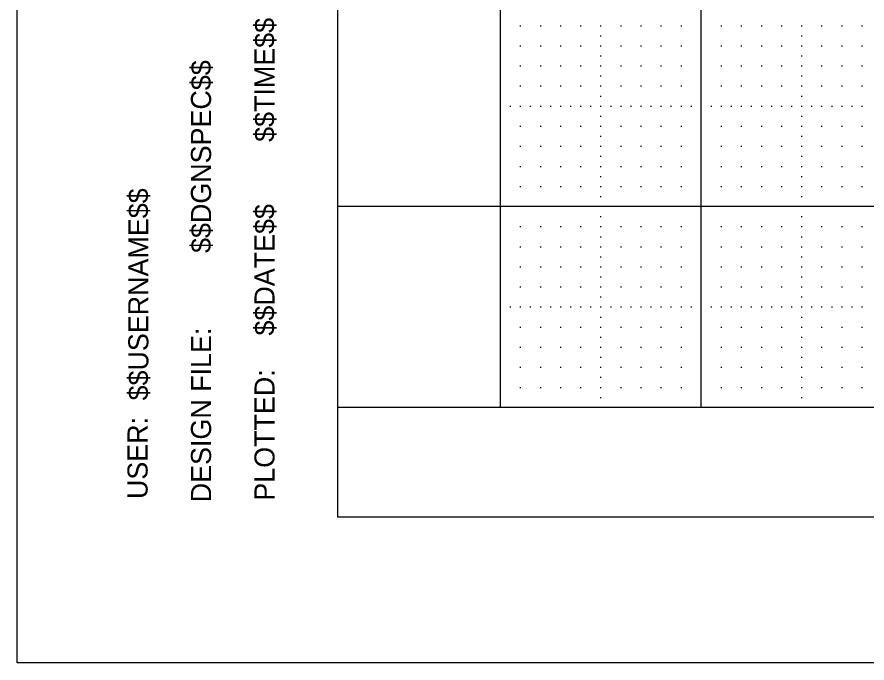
# Model space of a CAD drawing. Extents: x 0 to 34, y 0 to 22.
# Drawn here: x 0 to 4.231, y 0 to 3.215 of the extents above; entities that cross this region are included whole.
import ezdxf

# ---------------------------------------------------------------- set-up
doc = ezdxf.new("R2010")
doc.units = 0
for name, color, linetype in [('Level 1', 7, 'Continuous'), ('Level 4', 7, 'Continuous'), ('Level 5', 7, 'Continuous'), ('Level 63', 7, 'Continuous')]:
    doc.layers.add(name, color=color, linetype=linetype)

msp = doc.modelspace()

# ---------------------------------------------------------------- linework, layer by layer
at = {"layer": 'Level 1'}
for p, q in [((1.597, 0.726), (1.597, 21.272)), ((33.215, 0.726), (1.597, 0.726))]:
    msp.add_line(p, q, dxfattribs=at)
at = {"layer": 'Level 4'}
for p, q in [((2.406, 1.272), (2.406, 21.272)), ((3.406, 1.272), (3.406, 21.272)), ((33.215, 2.272), (1.597, 2.272)), ((33.215, 1.272), (1.597, 1.272))]:
    msp.add_line(p, q, dxfattribs=at)
at = {"layer": 'Level 5'}
for p, q in [((2.5035, 3.172), (2.5085, 3.172)), ((2.6035, 3.172), (2.6085, 3.172)), ((2.7035, 3.172), (2.7085, 3.172)), ((2.8035, 3.172), (2.8085, 3.172)), ((2.9035, 3.172), (2.9085, 3.172)), ((3.0035, 3.172), (3.0085, 3.172)), ((3.1035, 3.172), (3.1085, 3.172)), ((3.2035, 3.172), (3.2085, 3.172)), ((3.3035, 3.172), (3.3085, 3.172)), ((3.5035, 3.172), (3.5085, 3.172)), ((3.6035, 3.172), (3.6085, 3.172)), ((3.7035, 3.172), (3.7085, 3.172)), ((3.8035, 3.172), (3.8085, 3.172)), ((3.9035, 3.172), (3.9085, 3.172)), ((4.0035, 3.172), (4.0085, 3.172)), ((4.1035, 3.172), (4.1085, 3.172)), ((4.2035, 3.172), (4.2085, 3.172)), ((2.9035, 3.122), (2.9085, 3.122)), ((3.9035, 3.122), (3.9085, 3.122)), ((2.5035, 3.072), (2.5085, 3.072)), ((2.6035, 3.072), (2.6085, 3.072)), ((2.7035, 3.072), (2.7085, 3.072)), ((2.8035, 3.072), (2.8085, 3.072)), ((2.9035, 3.072), (2.9085, 3.072)), ((3.0035, 3.072), (3.0085, 3.072)), ((3.1035, 3.072), (3.1085, 3.072)), ((3.2035, 3.072), (3.2085, 3.072)), ((3.3035, 3.072), (3.3085, 3.072)), ((3.5035, 3.072), (3.5085, 3.072)), ((3.6035, 3.072), (3.6085, 3.072)), ((3.7035, 3.072), (3.7085, 3.072)), ((3.8035, 3.072), (3.8085, 3.072)), ((3.9035, 3.072), (3.9085, 3.072)), ((4.0035, 3.072), (4.0085, 3.072)), ((4.1035, 3.072), (4.1085, 3.072)), ((4.2035, 3.072), (4.2085, 3.072)), ((2.9035, 3.022), (2.9085, 3.022)), ((3.9035, 3.022), (3.9085, 3.022)), ((2.5035, 2.972), (2.5085, 2.972)), ((2.6035, 2.972), (2.6085, 2.972)), ((2.7035, 2.972), (2.7085, 2.972)), ((2.8035, 2.972), (2.8085, 2.972)), ((2.9035, 2.972), (2.9085, 2.972)), ((3.0035, 2.972), (3.0085, 2.972)), ((3.1035, 2.972), (3.1085, 2.972)), ((3.2035, 2.972), (3.2085, 2.972)), ((3.3035, 2.972), (3.3085, 2.972)), ((3.5035, 2.972), (3.5085, 2.972)), ((3.6035, 2.972), (3.6085, 2.972)), ((3.7035, 2.972), (3.7085, 2.972)), ((3.8035, 2.972), (3.8085, 2.972)), ((3.9035, 2.972), (3.9085, 2.972)), ((4.0035, 2.972), (4.0085, 2.972)), ((4.1035, 2.972), (4.1085, 2.972)), ((4.2035, 2.972), (4.2085, 2.972)), ((2.9035, 2.922), (2.9085, 2.922)), ((3.9035, 2.922), (3.9085, 2.922)), ((2.5035, 2.872), (2.5085, 2.872)), ((2.6035, 2.872), (2.6085, 2.872)), ((2.7035, 2.872), (2.7085, 2.872)), ((2.8035, 2.872), (2.8085, 2.872)), ((2.9035, 2.872), (2.9085, 2.872)), ((3.0035, 2.872), (3.0085, 2.872)), ((3.1035, 2.872), (3.1085, 2.872)), ((3.2035, 2.872), (3.2085, 2.872)), ((3.3035, 2.872), (3.3085, 2.872)), ((3.5035, 2.872), (3.5085, 2.872)), ((3.6035, 2.872), (3.6085, 2.872)), ((3.7035, 2.872), (3.7085, 2.872)), ((3.8035, 2.872), (3.8085, 2.872)), ((3.9035, 2.872), (3.9085, 2.872)), ((4.0035, 2.872), (4.0085, 2.872)), ((4.1035, 2.872), (4.1085, 2.872)), ((4.2035, 2.872), (4.2085, 2.872)), ((2.9035, 2.822), (2.9085, 2.822)), ((3.9035, 2.822), (3.9085, 2.822)), ((2.4535, 2.772), (2.4585, 2.772)), ((2.5035, 2.772), (2.5085, 2.772)), ((2.5535, 2.772), (2.5585, 2.772)), ((2.6035, 2.772), (2.6085, 2.772)), ((2.6535, 2.772), (2.6585, 2.772)), ((2.7035, 2.772), (2.7085, 2.772)), ((2.7535, 2.772), (2.7585, 2.772)), ((2.8035, 2.772), (2.8085, 2.772)), ((2.8535, 2.772), (2.8585, 2.772)), ((2.9035, 2.772), (2.9085, 2.772)), ((2.9535, 2.772), (2.9585, 2.772)), ((3.0035, 2.772), (3.0085, 2.772)), ((3.0535, 2.772), (3.0585, 2.772)), ((3.1035, 2.772), (3.1085, 2.772)), ((3.1535, 2.772), (3.1585, 2.772)), ((3.2035, 2.772), (3.2085, 2.772)), ((3.2535, 2.772), (3.2585, 2.772)), ((3.3035, 2.772), (3.3085, 2.772)), ((3.3535, 2.772), (3.3585, 2.772)), ((3.4535, 2.772), (3.4585, 2.772)), ((3.5035, 2.772), (3.5085, 2.772)), ((3.5535, 2.772), (3.5585, 2.772)), ((3.6035, 2.772), (3.6085, 2.772)), ((3.6535, 2.772), (3.6585, 2.772)), ((3.7035, 2.772), (3.7085, 2.772)), ((3.7535, 2.772), (3.7585, 2.772)), ((3.8035, 2.772), (3.8085, 2.772)), ((3.8535, 2.772), (3.8585, 2.772)), ((3.9035, 2.772), (3.9085, 2.772)), ((3.9535, 2.772), (3.9585, 2.772)), ((4.0035, 2.772), (4.0085, 2.772)), ((4.0535, 2.772), (4.0585, 2.772)), ((4.1035, 2.772), (4.1085, 2.772)), ((4.1535, 2.772), (4.1585, 2.772)), ((4.2035, 2.772), (4.2085, 2.772)), ((2.9035, 2.722), (2.9085, 2.722)), ((3.9035, 2.722), (3.9085, 2.722)), ((2.5035, 2.672), (2.5085, 2.672)), ((2.6035, 2.672), (2.6085, 2.672)), ((2.7035, 2.672), (2.7085, 2.672)), ((2.8035, 2.672), (2.8085, 2.672)), ((2.9035, 2.672), (2.9085, 2.672)), ((3.0035, 2.672), (3.0085, 2.672)), ((3.1035, 2.672), (3.1085, 2.672)), ((3.2035, 2.672), (3.2085, 2.672)), ((3.3035, 2.672), (3.3085, 2.672)), ((3.5035, 2.672), (3.5085, 2.672)), ((3.6035, 2.672), (3.6085, 2.672)), ((3.7035, 2.672), (3.7085, 2.672)), ((3.8035, 2.672), (3.8085, 2.672)), ((3.9035, 2.672), (3.9085, 2.672)), ((4.0035, 2.672), (4.0085, 2.672)), ((4.1035, 2.672), (4.1085, 2.672)), ((4.2035, 2.672), (4.2085, 2.672)), ((2.9035, 2.622), (2.9085, 2.622)), ((3.9035, 2.622), (3.9085, 2.622)), ((2.5035, 2.572), (2.5085, 2.572)), ((2.6035, 2.572), (2.6085, 2.572)), ((2.7035, 2.572), (2.7085, 2.572)), ((2.8035, 2.572), (2.8085, 2.572)), ((2.9035, 2.572), (2.9085, 2.572)), ((3.0035, 2.572), (3.0085, 2.572)), ((3.1035, 2.572), (3.1085, 2.572)), ((3.2035, 2.572), (3.2085, 2.572)), ((3.3035, 2.572), (3.3085, 2.572)), ((3.5035, 2.572), (3.5085, 2.572)), ((3.6035, 2.572), (3.6085, 2.572)), ((3.7035, 2.572), (3.7085, 2.572)), ((3.8035, 2.572), (3.8085, 2.572)), ((3.9035, 2.572), (3.9085, 2.572)), ((4.0035, 2.572), (4.0085, 2.572)), ((4.1035, 2.572), (4.1085, 2.572)), ((4.2035, 2.572), (4.2085, 2.572)), ((2.9035, 2.522), (2.9085, 2.522)), ((3.9035, 2.522), (3.9085, 2.522)), ((2.5035, 2.472), (2.5085, 2.472)), ((2.6035, 2.472), (2.6085, 2.472)), ((2.7035, 2.472), (2.7085, 2.472)), ((2.8035, 2.472), (2.8085, 2.472)), ((2.9035, 2.472), (2.9085, 2.472)), ((3.0035, 2.472), (3.0085, 2.472)), ((3.1035, 2.472), (3.1085, 2.472)), ((3.2035, 2.472), (3.2085, 2.472)), ((3.3035, 2.472), (3.3085, 2.472)), ((3.5035, 2.472), (3.5085, 2.472)), ((3.6035, 2.472), (3.6085, 2.472)), ((3.7035, 2.472), (3.7085, 2.472)), ((3.8035, 2.472), (3.8085, 2.472)), ((3.9035, 2.472), (3.9085, 2.472)), ((4.0035, 2.472), (4.0085, 2.472)), ((4.1035, 2.472), (4.1085, 2.472)), ((4.2035, 2.472), (4.2085, 2.472)), ((2.9035, 2.422), (2.9085, 2.422)), ((3.9035, 2.422), (3.9085, 2.422)), ((2.5035, 2.372), (2.5085, 2.372)), ((2.6035, 2.372), (2.6085, 2.372)), ((2.7035, 2.372), (2.7085, 2.372)), ((2.8035, 2.372), (2.8085, 2.372)), ((2.9035, 2.372), (2.9085, 2.372)), ((3.0035, 2.372), (3.0085, 2.372)), ((3.1035, 2.372), (3.1085, 2.372)), ((3.2035, 2.372), (3.2085, 2.372)), ((3.3035, 2.372), (3.3085, 2.372)), ((3.5035, 2.372), (3.5085, 2.372)), ((3.6035, 2.372), (3.6085, 2.372)), ((3.7035, 2.372), (3.7085, 2.372)), ((3.8035, 2.372), (3.8085, 2.372)), ((3.9035, 2.372), (3.9085, 2.372)), ((4.0035, 2.372), (4.0085, 2.372)), ((4.1035, 2.372), (4.1085, 2.372)), ((4.2035, 2.372), (4.2085, 2.372)), ((2.9035, 2.322), (2.9085, 2.322)), ((3.9035, 2.322), (3.9085, 2.322)), ((2.9035, 2.222), (2.9085, 2.222)), ((3.9035, 2.222), (3.9085, 2.222)), ((2.5035, 2.172), (2.5085, 2.172)), ((2.6035, 2.172), (2.6085, 2.172)), ((2.7035, 2.172), (2.7085, 2.172)), ((2.8035, 2.172), (2.8085, 2.172)), ((2.9035, 2.172), (2.9085, 2.172)), ((3.0035, 2.172), (3.0085, 2.172)), ((3.1035, 2.172), (3.1085, 2.172)), ((3.2035, 2.172), (3.2085, 2.172)), ((3.3035, 2.172), (3.3085, 2.172)), ((3.5035, 2.172), (3.5085, 2.172)), ((3.6035, 2.172), (3.6085, 2.172)), ((3.7035, 2.172), (3.7085, 2.172)), ((3.8035, 2.172), (3.8085, 2.172)), ((3.9035, 2.172), (3.9085, 2.172)), ((4.0035, 2.172), (4.0085, 2.172)), ((4.1035, 2.172), (4.1085, 2.172)), ((4.2035, 2.172), (4.2085, 2.172)), ((2.9035, 2.122), (2.9085, 2.122)), ((3.9035, 2.122), (3.9085, 2.122)), ((2.5035, 2.072), (2.5085, 2.072)), ((2.6035, 2.072), (2.6085, 2.072)), ((2.7035, 2.072), (2.7085, 2.072)), ((2.8035, 2.072), (2.8085, 2.072)), ((2.9035, 2.072), (2.9085, 2.072)), ((3.0035, 2.072), (3.0085, 2.072)), ((3.1035, 2.072), (3.1085, 2.072)), ((3.2035, 2.072), (3.2085, 2.072)), ((3.3035, 2.072), (3.3085, 2.072)), ((3.5035, 2.072), (3.5085, 2.072)), ((3.6035, 2.072), (3.6085, 2.072)), ((3.7035, 2.072), (3.7085, 2.072)), ((3.8035, 2.072), (3.8085, 2.072)), ((3.9035, 2.072), (3.9085, 2.072)), ((4.0035, 2.072), (4.0085, 2.072)), ((4.1035, 2.072), (4.1085, 2.072)), ((4.2035, 2.072), (4.2085, 2.072)), ((2.9035, 2.022), (2.9085, 2.022)), ((3.9035, 2.022), (3.9085, 2.022)), ((2.5035, 1.972), (2.5085, 1.972)), ((2.6035, 1.972), (2.6085, 1.972)), ((2.7035, 1.972), (2.7085, 1.972)), ((2.8035, 1.972), (2.8085, 1.972)), ((2.9035, 1.972), (2.9085, 1.972)), ((3.0035, 1.972), (3.0085, 1.972)), ((3.1035, 1.972), (3.1085, 1.972)), ((3.2035, 1.972), (3.2085, 1.972)), ((3.3035, 1.972), (3.3085, 1.972)), ((3.5035, 1.972), (3.5085, 1.972)), ((3.6035, 1.972), (3.6085, 1.972)), ((3.7035, 1.972), (3.7085, 1.972)), ((3.8035, 1.972), (3.8085, 1.972)), ((3.9035, 1.972), (3.9085, 1.972)), ((4.0035, 1.972), (4.0085, 1.972)), ((4.1035, 1.972), (4.1085, 1.972)), ((4.2035, 1.972), (4.2085, 1.972)), ((2.9035, 1.922), (2.9085, 1.922)), ((3.9035, 1.922), (3.9085, 1.922)), ((2.5035, 1.872), (2.5085, 1.872)), ((2.6035, 1.872), (2.6085, 1.872)), ((2.7035, 1.872), (2.7085, 1.872)), ((2.8035, 1.872), (2.8085, 1.872)), ((2.9035, 1.872), (2.9085, 1.872)), ((3.0035, 1.872), (3.0085, 1.872)), ((3.1035, 1.872), (3.1085, 1.872)), ((3.2035, 1.872), (3.2085, 1.872)), ((3.3035, 1.872), (3.3085, 1.872)), ((3.5035, 1.872), (3.5085, 1.872)), ((3.6035, 1.872), (3.6085, 1.872)), ((3.7035, 1.872), (3.7085, 1.872)), ((3.8035, 1.872), (3.8085, 1.872)), ((3.9035, 1.872), (3.9085, 1.872)), ((4.0035, 1.872), (4.0085, 1.872)), ((4.1035, 1.872), (4.1085, 1.872)), ((4.2035, 1.872), (4.2085, 1.872)), ((2.9035, 1.822), (2.9085, 1.822)), ((3.9035, 1.822), (3.9085, 1.822)), ((2.4535, 1.772), (2.4585, 1.772)), ((2.5035, 1.772), (2.5085, 1.772)), ((2.5535, 1.772), (2.5585, 1.772)), ((2.6035, 1.772), (2.6085, 1.772)), ((2.6535, 1.772), (2.6585, 1.772)), ((2.7035, 1.772), (2.7085, 1.772)), ((2.7535, 1.772), (2.7585, 1.772)), ((2.8035, 1.772), (2.8085, 1.772)), ((2.8535, 1.772), (2.8585, 1.772)), ((2.9035, 1.772), (2.9085, 1.772)), ((2.9535, 1.772), (2.9585, 1.772)), ((3.0035, 1.772), (3.0085, 1.772)), ((3.0535, 1.772), (3.0585, 1.772)), ((3.1035, 1.772), (3.1085, 1.772)), ((3.1535, 1.772), (3.1585, 1.772)), ((3.2035, 1.772), (3.2085, 1.772)), ((3.2535, 1.772), (3.2585, 1.772)), ((3.3035, 1.772), (3.3085, 1.772)), ((3.3535, 1.772), (3.3585, 1.772)), ((3.4535, 1.772), (3.4585, 1.772)), ((3.5035, 1.772), (3.5085, 1.772)), ((3.5535, 1.772), (3.5585, 1.772)), ((3.6035, 1.772), (3.6085, 1.772)), ((3.6535, 1.772), (3.6585, 1.772)), ((3.7035, 1.772), (3.7085, 1.772)), ((3.7535, 1.772), (3.7585, 1.772)), ((3.8035, 1.772), (3.8085, 1.772)), ((3.8535, 1.772), (3.8585, 1.772)), ((3.9035, 1.772), (3.9085, 1.772)), ((3.9535, 1.772), (3.9585, 1.772)), ((4.0035, 1.772), (4.0085, 1.772)), ((4.0535, 1.772), (4.0585, 1.772)), ((4.1035, 1.772), (4.1085, 1.772)), ((4.1535, 1.772), (4.1585, 1.772)), ((4.2035, 1.772), (4.2085, 1.772)), ((2.9035, 1.722), (2.9085, 1.722)), ((3.9035, 1.722), (3.9085, 1.722)), ((2.5035, 1.672), (2.5085, 1.672)), ((2.6035, 1.672), (2.6085, 1.672)), ((2.7035, 1.672), (2.7085, 1.672)), ((2.8035, 1.672), (2.8085, 1.672)), ((2.9035, 1.672), (2.9085, 1.672)), ((3.0035, 1.672), (3.0085, 1.672)), ((3.1035, 1.672), (3.1085, 1.672)), ((3.2035, 1.672), (3.2085, 1.672)), ((3.3035, 1.672), (3.3085, 1.672)), ((3.5035, 1.672), (3.5085, 1.672)), ((3.6035, 1.672), (3.6085, 1.672)), ((3.7035, 1.672), (3.7085, 1.672)), ((3.8035, 1.672), (3.8085, 1.672)), ((3.9035, 1.672), (3.9085, 1.672)), ((4.0035, 1.672), (4.0085, 1.672)), ((4.1035, 1.672), (4.1085, 1.672)), ((4.2035, 1.672), (4.2085, 1.672)), ((2.9035, 1.622), (2.9085, 1.622)), ((3.9035, 1.622), (3.9085, 1.622)), ((2.5035, 1.572), (2.5085, 1.572)), ((2.6035, 1.572), (2.6085, 1.572)), ((2.7035, 1.572), (2.7085, 1.572)), ((2.8035, 1.572), (2.8085, 1.572)), ((2.9035, 1.572), (2.9085, 1.572)), ((3.0035, 1.572), (3.0085, 1.572)), ((3.1035, 1.572), (3.1085, 1.572)), ((3.2035, 1.572), (3.2085, 1.572)), ((3.3035, 1.572), (3.3085, 1.572)), ((3.5035, 1.572), (3.5085, 1.572)), ((3.6035, 1.572), (3.6085, 1.572)), ((3.7035, 1.572), (3.7085, 1.572)), ((3.8035, 1.572), (3.8085, 1.572)), ((3.9035, 1.572), (3.9085, 1.572)), ((4.0035, 1.572), (4.0085, 1.572)), ((4.1035, 1.572), (4.1085, 1.572)), ((4.2035, 1.572), (4.2085, 1.572)), ((2.9035, 1.522), (2.9085, 1.522)), ((3.9035, 1.522), (3.9085, 1.522)), ((2.5035, 1.472), (2.5085, 1.472)), ((2.6035, 1.472), (2.6085, 1.472)), ((2.7035, 1.472), (2.7085, 1.472)), ((2.8035, 1.472), (2.8085, 1.472)), ((2.9035, 1.472), (2.9085, 1.472)), ((3.0035, 1.472), (3.0085, 1.472)), ((3.1035, 1.472), (3.1085, 1.472)), ((3.2035, 1.472), (3.2085, 1.472)), ((3.3035, 1.472), (3.3085, 1.472)), ((3.5035, 1.472), (3.5085, 1.472)), ((3.6035, 1.472), (3.6085, 1.472)), ((3.7035, 1.472), (3.7085, 1.472)), ((3.8035, 1.472), (3.8085, 1.472)), ((3.9035, 1.472), (3.9085, 1.472)), ((4.0035, 1.472), (4.0085, 1.472)), ((4.1035, 1.472), (4.1085, 1.472)), ((4.2035, 1.472), (4.2085, 1.472)), ((2.9035, 1.422), (2.9085, 1.422)), ((3.9035, 1.422), (3.9085, 1.422)), ((2.5035, 1.372), (2.5085, 1.372)), ((2.6035, 1.372), (2.6085, 1.372)), ((2.7035, 1.372), (2.7085, 1.372)), ((2.8035, 1.372), (2.8085, 1.372)), ((2.9035, 1.372), (2.9085, 1.372)), ((3.0035, 1.372), (3.0085, 1.372)), ((3.1035, 1.372), (3.1085, 1.372)), ((3.2035, 1.372), (3.2085, 1.372)), ((3.3035, 1.372), (3.3085, 1.372)), ((3.5035, 1.372), (3.5085, 1.372)), ((3.6035, 1.372), (3.6085, 1.372)), ((3.7035, 1.372), (3.7085, 1.372)), ((3.8035, 1.372), (3.8085, 1.372)), ((3.9035, 1.372), (3.9085, 1.372)), ((4.0035, 1.372), (4.0085, 1.372)), ((4.1035, 1.372), (4.1085, 1.372)), ((4.2035, 1.372), (4.2085, 1.372)), ((2.9035, 1.322), (2.9085, 1.322)), ((3.9035, 1.322), (3.9085, 1.322))]:
    msp.add_line(p, q, dxfattribs=at)
at = {"layer": 'Level 63'}
msp.add_lwpolyline([(0, 22), (34, 22), (34, 0), (0, 0)], close=True, dxfattribs=at)

# ---------------------------------------------------------------- texts
at = {"layer": 'Level 1'}
for s, height, p in [('$$TIME$$', 0.1, (1.282, 2.594)), ('$$DGNSPEC$$', 0.100002, (0.966, 2.041)), ('$$USERNAME$$', 0.100002, (0.654, 1.307)), ('$$DATE$$', 0.1, (1.282, 1.63)), ('DESIGN FILE:', 0.100002, (0.966, 0.8)), ('PLOTTED:', 0.1, (1.282, 0.808)), ('USER:', 0.1, (0.65, 0.816))]:
    msp.add_text(s, height=height, rotation=90, dxfattribs=at).set_placement(p)

doc.saveas('drawing.dxf')
